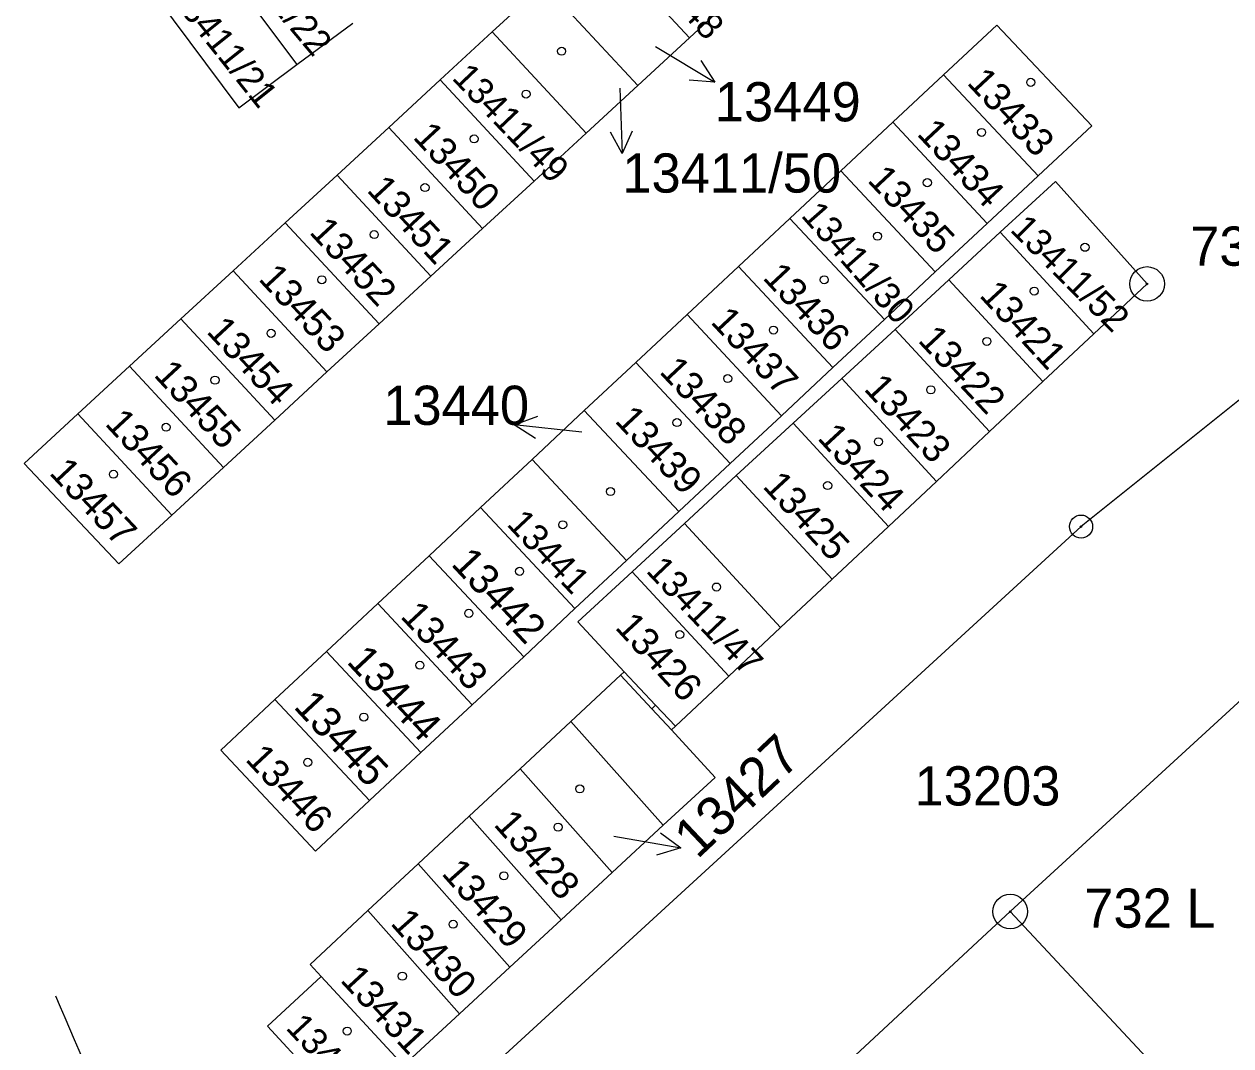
# Model space of a CAD drawing. Extents: x -822293 to -820259, y -1071573 to -1068794.
# Drawn here: x -820649.7 to -820597.4, y -1071147.9 to -1071103.6 of the extents above; entities that cross this region are included whole.
import ezdxf

# ---------------------------------------------------------------- set-up
doc = ezdxf.new("R2010")
doc.units = 0
for name, color, linetype in [('Vrstva 1', 7, 'Continuous'), ('Vrstva 10', 7, 'Continuous'), ('Vrstva 16', 7, 'Continuous'), ('Vrstva 17', 7, 'Continuous'), ('Vrstva 18', 7, 'Continuous'), ('Vrstva 19', 7, 'Continuous'), ('Vrstva 2', 7, 'Continuous'), ('Vrstva 24', 7, 'Continuous'), ('Vrstva 25', 7, 'Continuous'), ('Vrstva 3', 7, 'Continuous'), ('Vrstva 4', 7, 'Continuous')]:
    doc.layers.add(name, color=color, linetype=linetype)

msp = doc.modelspace()

# ---------------------------------------------------------------- linework, layer by layer
at = {"layer": 'Vrstva 1'}
for p, q in [((-820592.5, -1071116.26), (-820603.93, -1071125.41)), ((-820603.93, -1071125.41), (-820635.05, -1071153.94)), ((-820607, -1071142.1), (-820595.21, -1071131.28)), ((-820622.53, -1071133.31), (-820622.37, -1071133.15)), ((-820621.68, -1071134.22), (-820622.53, -1071133.31)), ((-820621.51, -1071134.06), (-820621.68, -1071134.22))]:
    msp.add_line(p, q, dxfattribs=at)
at = {"layer": 'Vrstva 10'}
msp.add_spline([(-820648.37, -1071145.75), (-820635.21, -1071175.92), (-820619.77, -1071208), (-820606.88, -1071231.72), (-820592.84, -1071254.92), (-820557.31, -1071306.48), (-820522.72, -1071349.67), (-820487.72, -1071388.36), (-820440.04, -1071434.15), (-820382.01, -1071481.32), (-820258.78, -1071573.12)], degree=3, dxfattribs=at)
at = {"layer": 'Vrstva 16'}
for p, q in [((-820622.37, -1071104.6), (-820619.8, -1071106.14)), ((-820623.92, -1071106.4), (-820623.81, -1071109.23)), ((-820625.57, -1071121.31), (-820628.5, -1071121)), ((-820624.17, -1071138.83), (-820621.28, -1071139.34))]:
    msp.add_line(p, q, dxfattribs=at)
for points in [[(-820620.4, -1071105.198), (-820619.8, -1071106.14), (-820620.913, -1071106.055)], [(-820623.375, -1071108.268), (-820623.81, -1071109.23), (-820624.318, -1071108.305)], [(-820627.575, -1071121.592), (-820628.5, -1071121), (-820627.472, -1071120.615)], [(-820622.158, -1071138.688), (-820621.28, -1071139.34), (-820622.328, -1071139.652)]]:
    msp.add_lwpolyline(points, dxfattribs=at)
at = {"layer": 'Vrstva 2'}
for p, q in [((-820641.91, -1071100.01), (-820637.92, -1071105.38)), ((-820624.97, -1071099.83), (-820620.9, -1071104.22)), ((-820644.43, -1071101.87), (-820640.43, -1071107.25)), ((-820629.45, -1071103.96), (-820627.21, -1071101.9)), ((-820623.14, -1071106.28), (-820627.21, -1071101.9)), ((-820620.9, -1071104.22), (-820618.67, -1071102.16)), ((-820637.92, -1071105.38), (-820635.49, -1071103.58)), ((-820631.7, -1071106.04), (-820629.45, -1071103.96)), ((-820625.38, -1071108.35), (-820629.45, -1071103.96)), ((-820607.58, -1071103.67), (-820609.89, -1071105.82)), ((-820603.47, -1071108.04), (-820607.58, -1071103.67)), ((-820620.9, -1071104.22), (-820623.14, -1071106.28)), ((-820640.43, -1071107.25), (-820637.92, -1071105.38)), ((-820633.93, -1071108.1), (-820631.7, -1071106.04)), ((-820631.7, -1071106.04), (-820627.63, -1071110.43)), ((-820609.89, -1071105.82), (-820612.09, -1071107.88)), ((-820609.89, -1071105.82), (-820605.79, -1071110.2)), ((-820625.38, -1071108.35), (-820623.14, -1071106.28)), ((-820636.17, -1071110.17), (-820633.93, -1071108.1)), ((-820633.93, -1071108.1), (-820629.87, -1071112.49)), ((-820612.09, -1071107.88), (-820614.34, -1071109.99)), ((-820612.09, -1071107.88), (-820608, -1071112.27)), ((-820605.79, -1071110.2), (-820603.47, -1071108.04)), ((-820627.63, -1071110.43), (-820625.38, -1071108.35)), ((-820638.42, -1071112.24), (-820636.17, -1071110.17)), ((-820636.17, -1071110.17), (-820632.11, -1071114.55)), ((-820616.55, -1071112.05), (-820614.34, -1071109.99)), ((-820614.34, -1071109.99), (-820610.25, -1071114.37)), ((-820608, -1071112.27), (-820605.79, -1071110.2)), ((-820627.63, -1071110.43), (-820629.87, -1071112.49)), ((-820605.04, -1071110.45), (-820607.43, -1071112.65)), ((-820601.07, -1071114.89), (-820605.04, -1071110.45)), ((-820640.67, -1071114.32), (-820638.42, -1071112.24)), ((-820638.42, -1071112.24), (-820634.35, -1071116.62)), ((-820616.55, -1071112.05), (-820618.78, -1071114.13)), ((-820612.45, -1071116.43), (-820616.55, -1071112.05)), ((-820610.25, -1071114.37), (-820608, -1071112.27)), ((-820629.87, -1071112.49), (-820632.11, -1071114.55)), ((-820607.43, -1071112.65), (-820609.66, -1071114.71)), ((-820603.37, -1071117.05), (-820607.43, -1071112.65)), ((-820642.94, -1071116.4), (-820640.67, -1071114.32)), ((-820640.67, -1071114.32), (-820636.61, -1071118.7)), ((-820618.78, -1071114.13), (-820621, -1071116.22)), ((-820618.78, -1071114.13), (-820614.68, -1071118.51)), ((-820612.45, -1071116.43), (-820610.25, -1071114.37)), ((-820632.11, -1071114.55), (-820634.35, -1071116.62)), ((-820609.66, -1071114.71), (-820611.99, -1071116.86)), ((-820609.66, -1071114.71), (-820605.58, -1071119.12)), ((-820603.37, -1071117.05), (-820601.07, -1071114.89)), ((-820645.16, -1071118.45), (-820642.94, -1071116.4)), ((-820642.94, -1071116.4), (-820638.87, -1071120.79)), ((-820621, -1071116.22), (-820623.23, -1071118.3)), ((-820621, -1071116.22), (-820616.91, -1071120.6)), ((-820614.68, -1071118.51), (-820612.45, -1071116.43)), ((-820634.35, -1071116.62), (-820636.61, -1071118.7)), ((-820611.99, -1071116.86), (-820614.3, -1071118.99)), ((-820611.99, -1071116.86), (-820607.9, -1071121.29)), ((-820605.58, -1071119.12), (-820603.37, -1071117.05)), ((-820647.4, -1071120.52), (-820645.16, -1071118.45)), ((-820645.16, -1071118.45), (-820641.09, -1071122.84)), ((-820623.23, -1071118.3), (-820625.46, -1071120.38)), ((-820623.23, -1071118.3), (-820619.14, -1071122.68)), ((-820616.91, -1071120.6), (-820614.68, -1071118.51)), ((-820636.61, -1071118.7), (-820638.87, -1071120.79)), ((-820614.3, -1071118.99), (-820616.41, -1071120.93)), ((-820614.3, -1071118.99), (-820610.19, -1071123.45)), ((-820607.9, -1071121.29), (-820605.58, -1071119.12)), ((-820649.73, -1071122.67), (-820647.4, -1071120.52)), ((-820647.4, -1071120.52), (-820643.33, -1071124.91)), ((-820625.46, -1071120.38), (-820627.72, -1071122.5)), ((-820625.46, -1071120.38), (-820621.36, -1071124.76)), ((-820619.14, -1071122.68), (-820616.91, -1071120.6)), ((-820638.87, -1071120.79), (-820641.09, -1071122.84)), ((-820616.41, -1071120.93), (-820618.87, -1071123.2)), ((-820616.41, -1071120.93), (-820612.28, -1071125.4)), ((-820610.19, -1071123.45), (-820607.9, -1071121.29)), ((-820645.63, -1071127.03), (-820649.73, -1071122.67)), ((-820627.72, -1071122.5), (-820629.95, -1071124.58)), ((-820627.72, -1071122.5), (-820623.63, -1071126.88)), ((-820621.36, -1071124.76), (-820619.14, -1071122.68)), ((-820641.09, -1071122.84), (-820643.33, -1071124.91)), ((-820618.87, -1071123.2), (-820614.72, -1071127.69)), ((-820612.28, -1071125.4), (-820610.19, -1071123.45)), ((-820629.95, -1071124.58), (-820632.18, -1071126.67)), ((-820629.95, -1071124.58), (-820625.86, -1071128.96)), ((-820623.63, -1071126.88), (-820621.36, -1071124.76)), ((-820643.33, -1071124.91), (-820645.63, -1071127.03)), ((-820623.38, -1071127.37), (-820621.12, -1071125.28)), ((-820621.12, -1071125.28), (-820616.96, -1071129.79)), ((-820614.72, -1071127.69), (-820612.28, -1071125.4)), ((-820632.18, -1071126.67), (-820634.41, -1071128.75)), ((-820632.18, -1071126.67), (-820628.08, -1071131.05)), ((-820625.86, -1071128.96), (-820623.63, -1071126.88)), ((-820625.74, -1071129.54), (-820623.38, -1071127.37)), ((-820623.38, -1071127.37), (-820619.2, -1071131.89)), ((-820634.41, -1071128.75), (-820636.63, -1071130.83)), ((-820634.41, -1071128.75), (-820630.31, -1071133.13)), ((-820628.08, -1071131.05), (-820625.86, -1071128.96)), ((-820623.73, -1071131.7), (-820625.74, -1071129.54)), ((-820616.96, -1071129.79), (-820619.2, -1071131.89)), ((-820636.63, -1071130.83), (-820638.86, -1071132.91)), ((-820636.63, -1071130.83), (-820632.54, -1071135.21)), ((-820630.31, -1071133.13), (-820628.08, -1071131.05)), ((-820622.37, -1071133.15), (-820623.73, -1071131.7)), ((-820619.2, -1071131.89), (-820621.51, -1071134.06)), ((-820638.86, -1071132.91), (-820641.2, -1071135.1)), ((-820638.86, -1071132.91), (-820634.77, -1071137.29)), ((-820632.54, -1071135.21), (-820630.31, -1071133.13)), ((-820626.04, -1071133.86), (-820628.24, -1071135.91)), ((-820622.04, -1071138.36), (-820626.04, -1071133.86)), ((-820641.2, -1071135.1), (-820637.11, -1071139.48)), ((-820634.77, -1071137.29), (-820632.54, -1071135.21)), ((-820628.24, -1071135.91), (-820630.45, -1071137.97)), ((-820624.25, -1071140.4), (-820628.24, -1071135.91)), ((-820637.11, -1071139.48), (-820634.77, -1071137.29)), ((-820630.45, -1071137.97), (-820632.66, -1071140.03)), ((-820626.46, -1071142.46), (-820630.45, -1071137.97)), ((-820624.25, -1071140.4), (-820622.04, -1071138.36)), ((-820632.66, -1071140.03), (-820634.84, -1071142.06)), ((-820628.68, -1071144.51), (-820632.66, -1071140.03)), ((-820626.46, -1071142.46), (-820624.25, -1071140.4)), ((-820634.84, -1071142.06), (-820637.34, -1071144.39)), ((-820630.87, -1071146.53), (-820634.84, -1071142.06)), ((-820613.71, -1071148.32), (-820607, -1071142.1)), ((-820607, -1071142.1), (-820598.65, -1071151.04)), ((-820628.68, -1071144.51), (-820626.46, -1071142.46)), ((-820637.34, -1071144.39), (-820636.86, -1071144.91)), ((-820630.87, -1071146.53), (-820628.68, -1071144.51)), ((-820639.19, -1071147.07), (-820636.86, -1071144.91)), ((-820636.86, -1071144.91), (-820633.29, -1071148.77)), ((-820633.29, -1071148.77), (-820630.87, -1071146.53)), ((-820635.62, -1071150.93), (-820639.19, -1071147.07))]:
    msp.add_line(p, q, dxfattribs=at)
at = {"layer": 'Vrstva 24'}
for centre, radius in [((-820601.07, -1071114.89), 0.75), ((-820601.07, -1071114.89), 0.0327), ((-820603.93, -1071125.41), 0.5), ((-820603.93, -1071125.41), 0.0327), ((-820607, -1071142.1), 0.75), ((-820607, -1071142.1), 0.0327)]:
    msp.add_circle(centre, radius, dxfattribs=at)
at = {"layer": 'Vrstva 25'}
for centre in [(-820626.44, -1071104.8), (-820606.11, -1071106.15), (-820627.98, -1071106.66), (-820608.24, -1071108.32), (-820630.23, -1071108.6), (-820632.36, -1071110.71), (-820610.59, -1071110.5), (-820634.56, -1071112.75), (-820612.75, -1071112.82), (-820603.76, -1071113.3), (-820636.83, -1071114.71), (-820615.06, -1071114.71), (-820605.96, -1071115.2), (-820639.03, -1071117.03), (-820617.26, -1071116.89), (-820608.01, -1071117.38), (-820641.46, -1071119.06), (-820619.24, -1071118.99), (-820610.44, -1071119.48), (-820643.58, -1071121.1), (-820621.44, -1071120.9), (-820612.71, -1071121.73), (-820645.86, -1071123.14), (-820624.32, -1071123.89), (-820614.91, -1071123.63), (-820626.39, -1071125.33), (-820628.26, -1071127.35), (-820619.73, -1071128.03), (-820630.46, -1071129.17), (-820621.32, -1071130.09), (-820632.58, -1071131.42), (-820635.01, -1071133.67), (-820637.44, -1071135.63), (-820625.65, -1071136.78), (-820626.59, -1071138.44), (-820628.94, -1071140.55), (-820631.14, -1071142.65), (-820633.34, -1071144.9), (-820635.73, -1071147.28)]:
    msp.add_circle(centre, 0.175, dxfattribs=at)
at = {"layer": 'Vrstva 3'}
msp.add_line((-820622.37, -1071133.15), (-820621.51, -1071134.06), dxfattribs=at)
at = {"layer": 'Vrstva 4'}
for p, q in [((-820621.12, -1071125.28), (-820618.87, -1071123.2)), ((-820616.96, -1071129.79), (-820614.72, -1071127.69)), ((-820626.04, -1071133.86), (-820623.89, -1071131.85)), ((-820623.89, -1071131.85), (-820623.73, -1071131.7)), ((-820623.89, -1071131.85), (-820622.53, -1071133.31)), ((-820619.78, -1071136.28), (-820621.68, -1071134.22)), ((-820622.04, -1071138.36), (-820619.78, -1071136.28))]:
    msp.add_line(p, q, dxfattribs=at)

# ---------------------------------------------------------------- texts
at = {"layer": 'Vrstva 16'}
for s, p in [('13449', (-820619.8, -1071107.84)), ('13411/50', (-820623.81, -1071110.93)), ('13440', (-820634.169, -1071121))]:
    msp.add_text(s, height=1.7, dxfattribs=at).set_placement(p)
msp.add_text('13427', height=1.7, rotation=43.3634, dxfattribs=at).set_placement((-820620.56, -1071139.86))
at = {"layer": 'Vrstva 17'}
for s, p in [('733 L', (-820599.2, -1071114.1)), ('732 L', (-820603.79, -1071142.8))]:
    msp.add_text(s, height=1.7, dxfattribs=at).set_placement(p)
at = {"layer": 'Vrstva 18'}
msp.add_text('13203', height=1.7, dxfattribs=at).set_placement((-820611.146, -1071137.5))
at = {"layer": 'Vrstva 19'}
for s, height, rotation, p in [('13411/48', 1.139, 312.3028, (-820624.43, -1071099.69)), ('13411/22', 1.139, 310.0976, (-820641.27, -1071100.24)), ('13411/21', 1.139, 308.6017, (-820643.51, -1071102.38)), ('13411/49', 1.139, 313.5484, (-820631.23, -1071105.99)), ('13433', 1.2, 313.0699, (-820608.914, -1071106.197)), ('13450', 1.2, 312.8369, (-820632.925, -1071108.549)), ('13434', 1.2, 313.0693, (-820611.084, -1071108.409)), ('13435', 1.2, 313.0709, (-820613.23, -1071110.422)), ('13451', 1.2, 312.8384, (-820634.919, -1071110.855)), ('13411/30', 1.139, 311.2581, (-820616.1, -1071111.94)), ('13452', 1.2, 312.8383, (-820637.411, -1071112.672)), ('13411/52', 1.139, 315.2182, (-820607.05, -1071112.58)), ('13453', 1.2, 312.8366, (-820639.615, -1071114.697)), ('13436', 1.2, 313.0694, (-820617.764, -1071114.649)), ('13421', 1.2, 312.6906, (-820608.375, -1071115.413)), ('13437', 1.2, 313.0709, (-820620.021, -1071116.563)), ('13454', 1.2, 312.8385, (-820641.866, -1071116.979)), ('13422', 1.2, 313.1386, (-820611.036, -1071117.368)), ('13455', 1.2, 312.8368, (-820644.151, -1071118.862)), ('13438', 1.2, 313.0709, (-820622.243, -1071118.719)), ('13423', 1.2, 312.6911, (-820613.381, -1071119.464)), ('13456', 1.2, 312.8382, (-820646.266, -1071120.979)), ('13439', 1.2, 313.0691, (-820624.174, -1071120.849)), ('13424', 1.2, 312.6914, (-820615.392, -1071121.597)), ('13457', 1.2, 313.2462, (-820648.681, -1071123.111)), ('13425', 1.2, 312.692, (-820617.768, -1071123.689)), ('13441', 1.139, 313.1748, (-820628.86, -1071125.33)), ('13442', 1.3, 313.0704, (-820631.27, -1071127.057)), ('13411/47', 1.139, 313.5312, (-820622.82, -1071127.36)), ('13443', 1.2, 313.0687, (-820633.464, -1071129.329)), ('13426', 1.2, 312.6914, (-820624.162, -1071129.807)), ('13444', 1.3, 313.0701, (-820635.794, -1071131.295)), ('13445', 1.3, 313.07, (-820638.09, -1071133.248)), ('13446', 1.2, 313.07, (-820640.185, -1071135.53)), ('13428', 1.2, 311.6483, (-820629.419, -1071138.346)), ('13429', 1.2, 311.6455, (-820631.68, -1071140.467)), ('13430', 1.2, 311.644, (-820633.893, -1071142.632)), ('13431', 1.2, 312.7763, (-820636.071, -1071145.099)), ('13432', 1.139, 312.9521, (-820638.43, -1071147.17))]:
    msp.add_text(s, height=height, rotation=rotation, dxfattribs=at).set_placement(p)
for s, p in [('13449', (-820622.37, -1071104.6)), ('13411/50', (-820623.92, -1071106.4)), ('13440', (-820625.57, -1071121.31)), ('13427', (-820624.17, -1071138.83))]:
    msp.add_text(s, height=0.005, dxfattribs=at).set_placement(p)

doc.saveas('drawing.dxf')
